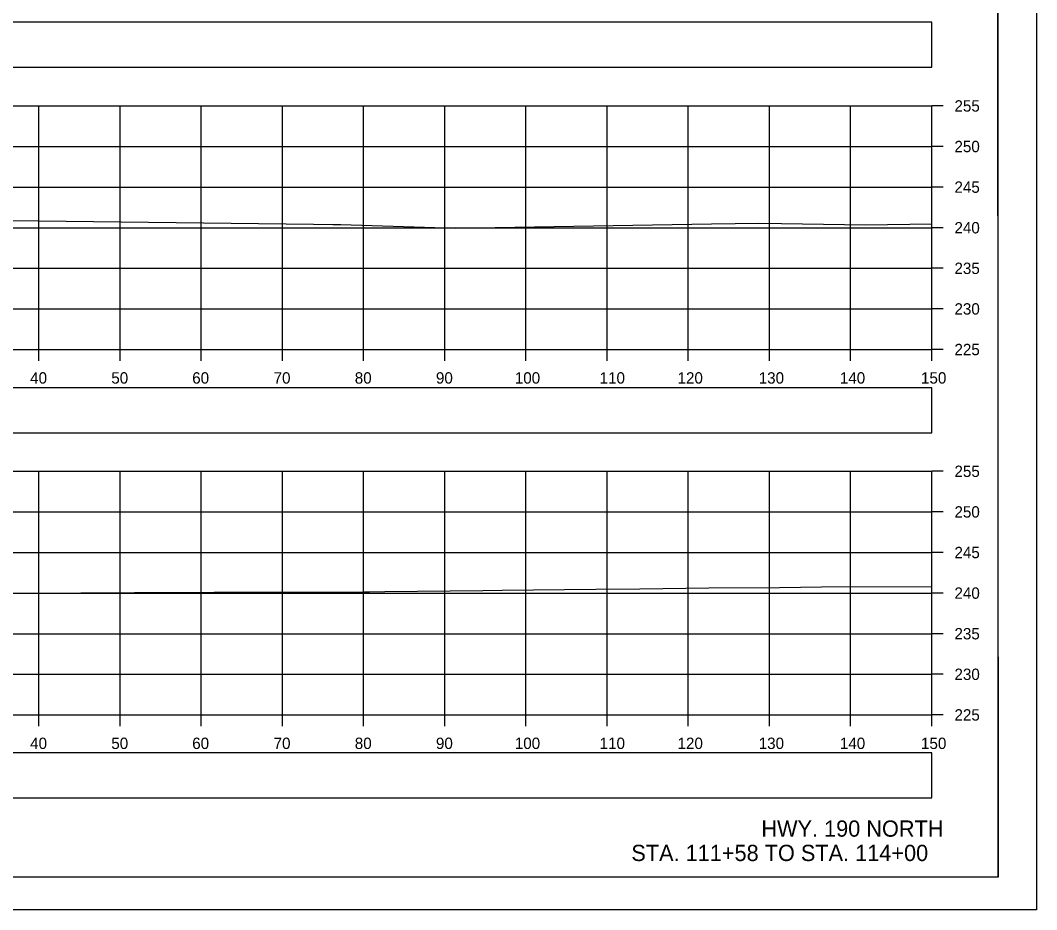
# Model space of a CAD drawing. Extents: x 1369627 to 1374022, y 380035 to 398173.
# Drawn here: x 1370216.9 to 1370342.2, y 381101.6 to 381211.1 of the extents above; entities that cross this region are included whole.
import ezdxf

# ---------------------------------------------------------------- set-up
doc = ezdxf.new("R2010")
doc.units = 0
for name, color, linetype in [('Default', 7, 'Continuous'), ('R_Axis', 7, 'Continuous'), ('R_Axis Annot', 7, 'Continuous'), ('R_Border', 7, 'Continuous'), ('R_Draft', 7, 'Continuous'), ('R_Exist Surface', 7, 'Continuous'), ('R_Grid', 7, 'Continuous'), ('R_No Plot', 7, 'Continuous')]:
    doc.layers.add(name, color=color, linetype=linetype)

msp = doc.modelspace()

# ---------------------------------------------------------------- linework, layer by layer
at = {"layer": 'Default'}
for points in [[(1370029.24, 381205.33), (1370329.24, 381205.33), (1370329.24, 381210.85), (1370029.24, 381210.85)], [(1370029.24, 381160.29), (1370329.24, 381160.29), (1370329.24, 381165.82), (1370029.24, 381165.82)], [(1370029.24, 381115.34), (1370329.24, 381115.34), (1370329.24, 381120.87), (1370029.24, 381120.87)]]:
    msp.add_lwpolyline(points, close=True, dxfattribs=at)
at = {"layer": 'R_Axis'}
for p, q in [((1370329.24, 381170.55), (1370329.24, 381200.55)), ((1370330.64, 381200.55), (1370329.24, 381200.55)), ((1370330.64, 381195.55), (1370329.24, 381195.55)), ((1370330.64, 381190.55), (1370329.24, 381190.55)), ((1370330.64, 381185.55), (1370329.24, 381185.55)), ((1370330.64, 381180.55), (1370329.24, 381180.55)), ((1370330.64, 381175.55), (1370329.24, 381175.55)), ((1370029.24, 381170.55), (1370329.24, 381170.55)), ((1370219.24, 381169.15), (1370219.24, 381170.55)), ((1370229.24, 381169.15), (1370229.24, 381170.55)), ((1370239.24, 381169.15), (1370239.24, 381170.55)), ((1370249.24, 381169.15), (1370249.24, 381170.55)), ((1370259.24, 381169.15), (1370259.24, 381170.55)), ((1370269.24, 381169.15), (1370269.24, 381170.55)), ((1370279.24, 381169.15), (1370279.24, 381170.55)), ((1370289.24, 381169.15), (1370289.24, 381170.55)), ((1370299.24, 381169.15), (1370299.24, 381170.55)), ((1370309.24, 381169.15), (1370309.24, 381170.55)), ((1370319.24, 381169.15), (1370319.24, 381170.55)), ((1370329.24, 381169.15), (1370329.24, 381170.55)), ((1370330.64, 381170.55), (1370329.24, 381170.55)), ((1370329.24, 381125.55), (1370329.24, 381155.55)), ((1370330.64, 381155.55), (1370329.24, 381155.55)), ((1370330.64, 381150.55), (1370329.24, 381150.55)), ((1370330.64, 381145.55), (1370329.24, 381145.55)), ((1370330.64, 381140.55), (1370329.24, 381140.55)), ((1370330.64, 381135.55), (1370329.24, 381135.55)), ((1370330.64, 381130.55), (1370329.24, 381130.55)), ((1370029.24, 381125.55), (1370329.24, 381125.55)), ((1370219.24, 381124.15), (1370219.24, 381125.55)), ((1370229.24, 381124.15), (1370229.24, 381125.55)), ((1370239.24, 381124.15), (1370239.24, 381125.55)), ((1370249.24, 381124.15), (1370249.24, 381125.55)), ((1370259.24, 381124.15), (1370259.24, 381125.55)), ((1370269.24, 381124.15), (1370269.24, 381125.55)), ((1370279.24, 381124.15), (1370279.24, 381125.55)), ((1370289.24, 381124.15), (1370289.24, 381125.55)), ((1370299.24, 381124.15), (1370299.24, 381125.55)), ((1370309.24, 381124.15), (1370309.24, 381125.55)), ((1370319.24, 381124.15), (1370319.24, 381125.55)), ((1370329.24, 381124.15), (1370329.24, 381125.55)), ((1370330.64, 381125.55), (1370329.24, 381125.55))]:
    msp.add_line(p, q, dxfattribs=at)
at = {"layer": 'R_Border'}
for q in [(1370337.42, 381311.01), (1370021.24, 381105.55)]:
    msp.add_line((1370337.42, 381105.55), q, dxfattribs=at)
at = {"layer": 'R_Exist Surface'}
for points in [[(1370202.23, 381186.6), (1370253.06, 381186), (1370255.44, 381185.96), (1370256.42, 381185.93), (1370270.62, 381185.51), (1370302.11, 381186.03), (1370307.95, 381186.13), (1370310.72, 381186.08), (1370321.06, 381185.92), (1370329.24, 381186.01)], [(1370209.13, 381140.49), (1370217.1, 381140.54), (1370224.39, 381140.57), (1370231.01, 381140.61), (1370240.82, 381140.65), (1370245.17, 381140.68), (1370259.33, 381140.71), (1370259.84, 381140.71), (1370259.96, 381140.71), (1370261.86, 381140.74), (1370273.91, 381140.88), (1370276.31, 381140.9), (1370287.85, 381141.03), (1370293.27, 381141.08), (1370301.77, 381141.18), (1370310.5, 381141.26), (1370315.67, 381141.32), (1370329.24, 381141.36)]]:
    msp.add_lwpolyline(points, dxfattribs=at)
at = {"layer": 'R_Grid'}
for p, q in [((1370029.24, 381200.55), (1370329.24, 381200.55)), ((1370219.24, 381170.55), (1370219.24, 381200.55)), ((1370229.24, 381170.55), (1370229.24, 381200.55)), ((1370239.24, 381170.55), (1370239.24, 381200.55)), ((1370249.24, 381170.55), (1370249.24, 381200.55)), ((1370259.24, 381170.55), (1370259.24, 381200.55)), ((1370269.24, 381170.55), (1370269.24, 381200.55)), ((1370279.24, 381170.55), (1370279.24, 381200.55)), ((1370289.24, 381170.55), (1370289.24, 381200.55)), ((1370299.24, 381170.55), (1370299.24, 381200.55)), ((1370309.24, 381170.55), (1370309.24, 381200.55)), ((1370319.24, 381170.55), (1370319.24, 381200.55)), ((1370329.24, 381170.55), (1370329.24, 381200.55)), ((1370029.24, 381195.55), (1370329.24, 381195.55)), ((1370029.24, 381190.55), (1370329.24, 381190.55)), ((1370029.24, 381185.55), (1370329.24, 381185.55)), ((1370029.24, 381180.55), (1370329.24, 381180.55)), ((1370029.24, 381175.55), (1370329.24, 381175.55)), ((1370029.24, 381170.55), (1370329.24, 381170.55)), ((1370029.24, 381155.55), (1370329.24, 381155.55)), ((1370219.24, 381125.55), (1370219.24, 381155.55)), ((1370229.24, 381125.55), (1370229.24, 381155.55)), ((1370239.24, 381125.55), (1370239.24, 381155.55)), ((1370249.24, 381125.55), (1370249.24, 381155.55)), ((1370259.24, 381125.55), (1370259.24, 381155.55)), ((1370269.24, 381125.55), (1370269.24, 381155.55)), ((1370279.24, 381125.55), (1370279.24, 381155.55)), ((1370289.24, 381125.55), (1370289.24, 381155.55)), ((1370299.24, 381125.55), (1370299.24, 381155.55)), ((1370309.24, 381125.55), (1370309.24, 381155.55)), ((1370319.24, 381125.55), (1370319.24, 381155.55)), ((1370329.24, 381125.55), (1370329.24, 381155.55)), ((1370029.24, 381150.55), (1370329.24, 381150.55)), ((1370029.24, 381145.55), (1370329.24, 381145.55)), ((1370029.24, 381140.55), (1370329.24, 381140.55)), ((1370029.24, 381135.55), (1370329.24, 381135.55)), ((1370029.24, 381130.55), (1370329.24, 381130.55)), ((1370029.24, 381125.55), (1370329.24, 381125.55))]:
    msp.add_line(p, q, dxfattribs=at)
at = {"layer": 'R_No Plot'}
msp.add_line((1370008.84, 381101.57), (1370342.17, 381101.57), dxfattribs=at)
for points in [[(1370008.83, 381314.9), (1370342.17, 381314.9), (1370342.17, 381101.56), (1370008.83, 381101.56)], [(1370255.16, 381311.01), (1370274.78, 381311.01), (1370274.78, 381301.13), (1370290.89, 381301.13), (1370314.09, 381301.13), (1370314.09, 381268.46), (1370337.3, 381268.46), (1370337.42, 381105.55), (1370021.24, 381105.55), (1370021.24, 381311.01)]]:
    msp.add_lwpolyline(points, close=True, dxfattribs=at)

# ---------------------------------------------------------------- texts
at = {"layer": 'R_Axis Annot'}
for s, p in [('255', (1370332.04, 381199.85)), ('250', (1370332.04, 381194.85)), ('245', (1370332.04, 381189.85)), ('240', (1370332.04, 381184.85)), ('235', (1370332.04, 381179.85)), ('230', (1370332.04, 381174.85)), ('225', (1370332.04, 381169.85)), ('40', (1370218.15, 381166.35)), ('50', (1370228.15, 381166.35)), ('60', (1370238.12, 381166.35)), ('70', (1370248.15, 381166.35)), ('80', (1370258.15, 381166.35)), ('90', (1370268.15, 381166.35)), ('100', (1370277.87, 381166.35)), ('110', (1370288.32, 381166.35)), ('120', (1370297.92, 381166.35)), ('130', (1370307.92, 381166.35)), ('140', (1370317.92, 381166.35)), ('150', (1370327.92, 381166.35)), ('255', (1370332.04, 381154.85)), ('250', (1370332.04, 381149.85)), ('245', (1370332.04, 381144.85)), ('240', (1370332.04, 381139.85)), ('235', (1370332.04, 381134.85)), ('230', (1370332.04, 381129.85)), ('225', (1370332.04, 381124.85)), ('40', (1370218.15, 381121.35)), ('50', (1370228.15, 381121.35)), ('60', (1370238.12, 381121.35)), ('70', (1370248.15, 381121.35)), ('80', (1370258.15, 381121.35)), ('90', (1370268.15, 381121.35)), ('100', (1370277.87, 381121.35)), ('110', (1370288.32, 381121.35)), ('120', (1370297.92, 381121.35)), ('130', (1370307.92, 381121.35)), ('140', (1370317.92, 381121.35)), ('150', (1370327.92, 381121.35))]:
    msp.add_text(s, height=1.4, dxfattribs=at).set_placement(p)
at = {"layer": 'R_Draft'}
for s, p in [('HWY. 190 NORTH', (1370308.25, 381110.55)), ('STA. 111+58 TO STA. 114+00', (1370292.23, 381107.55))]:
    msp.add_text(s, height=2, dxfattribs=at).set_placement(p)

doc.saveas('drawing.dxf')
